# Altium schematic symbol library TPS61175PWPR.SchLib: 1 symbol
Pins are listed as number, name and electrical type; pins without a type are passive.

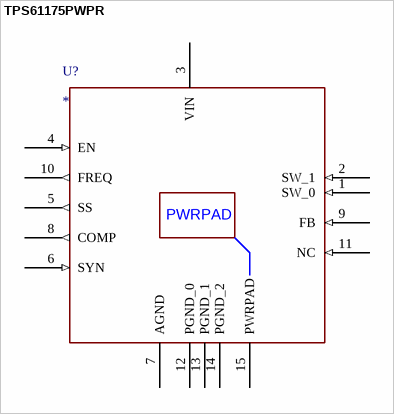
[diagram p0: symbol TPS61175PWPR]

## TPS61175PWPR
designator U?
GENERIC PART DESCRIPTION: 3-A High Voltage Boost Converter with Soft-start and Programmable Switching Frequency; ORDERABLE DEVICE NUMBER: TPS61175PWPR
footprint HTSSOP_PWP14_EP2P46X2P31
pins: 1 SW_0 (in), 2 SW_1 (in), 3 VIN (power), 4 EN (in), 5 SS (out), 6 SYN (in), 7 AGND (power), 8 COMP (out), 9 FB (in), 10 FREQ (out), 11 NC (in), 12 PGND_0 (power), 13 PGND_1 (power), 14 PGND_2 (power), 15 PWRPAD (power)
